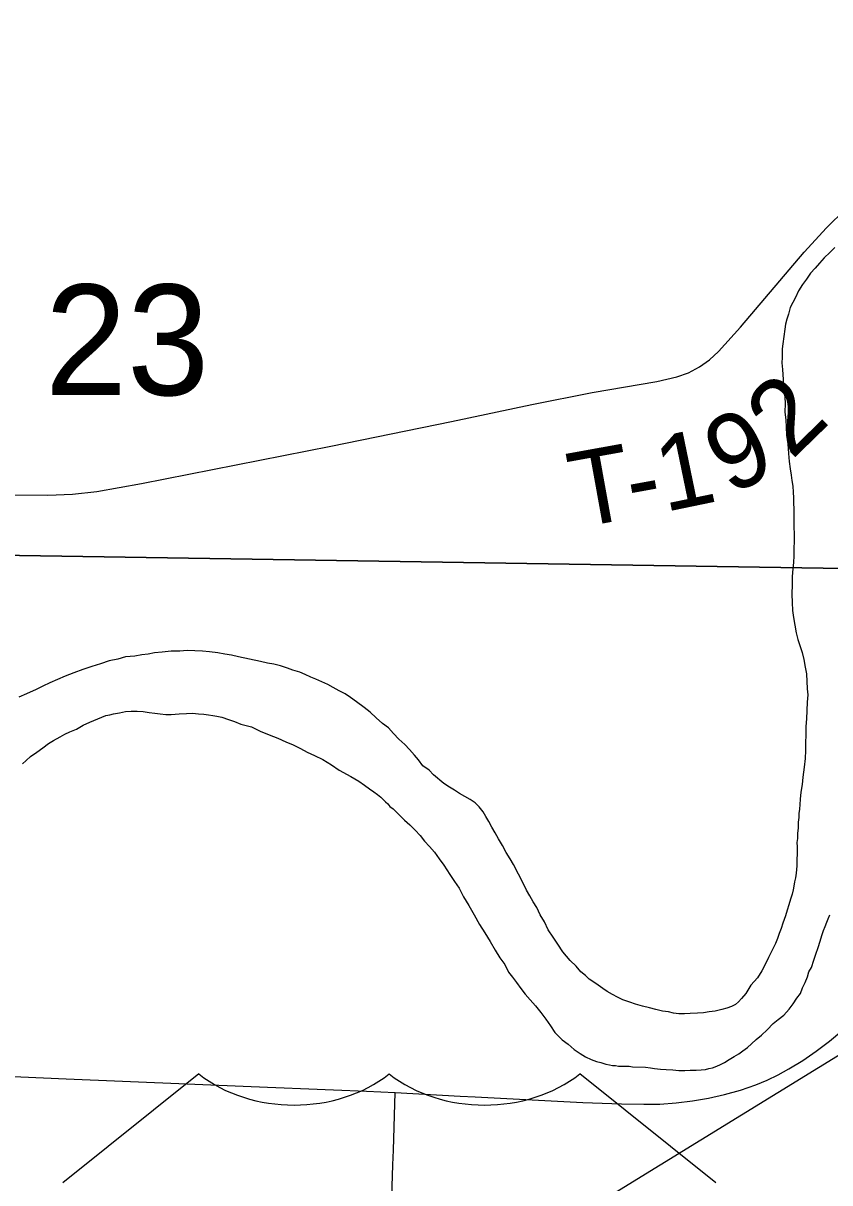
# Model space of a CAD drawing. Extents: x 2.4 to 73.1, y 4.5 to 25.6.
# Drawn here: x 30.0992 to 30.4044, y 20.9019 to 21.3407 of the extents above; entities that cross this region are included whole.
import ezdxf

# ---------------------------------------------------------------- set-up
doc = ezdxf.new("R2010")
doc.units = 0
for name, color, linetype in [('GM_X_County_Road', 7, 'Continuous'), ('GM_X_Major_River', 7, 'Continuous'), ('GM_X_Rail_Line', 7, 'Continuous'), ('GM_X_Section', 7, 'Continuous'), ('GM_X_Section_Text', 7, 'Continuous'), ('GM_X_Township_Road', 7, 'Continuous'), ('GM_X_Township_Road_Text', 7, 'Continuous'), ('GM_X_US_Route', 7, 'Continuous'), ('GM_X_US_Shield', 7, 'Continuous')]:
    doc.layers.add(name, color=color, linetype=linetype)

msp = doc.modelspace()

# ---------------------------------------------------------------- linework, layer by layer
at = {"layer": 'GM_X_County_Road'}
for points in [[(29.98929, 20.94555), (29.98973, 20.94555), (30.01271, 20.94578), (30.02518, 20.94536), (30.0781, 20.9429), (30.11546, 20.94119), (30.18551, 20.93827), (30.21656, 20.93706)], [(30.21656, 20.93706), (30.22911, 20.93657), (30.23998, 20.93603)]]:
    msp.add_lwpolyline(points, dxfattribs=at)
at = {"layer": 'GM_X_Major_River'}
for points in [[(30.40633, 21.25576), (30.40439, 21.2539), (30.40225, 21.25186), (30.40049, 21.24981), (30.39893, 21.24795), (30.39718, 21.24609), (30.39561, 21.24384), (30.39404, 21.24179), (30.39265, 21.23935), (30.39146, 21.23691), (30.39047, 21.23503), (30.38947, 21.23315), (30.38884, 21.23051), (30.38823, 21.22862), (30.38762, 21.22674), (30.38739, 21.22484), (30.38669, 21.21935), (30.38646, 21.21745), (30.38642, 21.21575), (30.38639, 21.21423), (30.38634, 21.21214), (30.38647, 21.20967), (30.38662, 21.20776), (30.38677, 21.20586), (30.38691, 21.20358), (30.38705, 21.20148), (30.38738, 21.1992), (30.38751, 21.19672), (30.38744, 21.1935), (30.38776, 21.19064), (30.38788, 21.18779), (30.38801, 21.18475), (30.3885, 21.1815), (30.3888, 21.17789), (30.38911, 21.17484), (30.38943, 21.17199), (30.38976, 21.1697), (30.39009, 21.1676), (30.39042, 21.1655), (30.39056, 21.16322), (30.39071, 21.16113), (30.39066, 21.15904), (30.3908, 21.15695), (30.39076, 21.15486), (30.39088, 21.15201), (30.39083, 21.14992), (30.39097, 21.14745), (30.39091, 21.14479), (30.39084, 21.14175), (30.39078, 21.13909)], [(30.39078, 21.13909), (30.39073, 21.13662), (30.39048, 21.13416), (30.39023, 21.13131), (30.39016, 21.12828), (30.39008, 21.12467), (30.39019, 21.12144), (30.39032, 21.1184), (30.39064, 21.11573), (30.39114, 21.11287), (30.39165, 21.11001), (30.39235, 21.10752), (30.39306, 21.10522), (30.39395, 21.10255), (30.39465, 21.09987), (30.39516, 21.09701), (30.39567, 21.09453), (30.39593, 21.08882), (30.39606, 21.08654), (30.39581, 21.0837), (30.39574, 21.08066), (30.39567, 21.07743), (30.39542, 21.07459), (30.39534, 21.07136), (30.39527, 21.06832), (30.39521, 21.06547), (30.39514, 21.06243), (30.39469, 21.05922), (30.39423, 21.05543), (30.39397, 21.05258), (30.39353, 21.04974), (30.39328, 21.04709), (30.39304, 21.04501), (30.393, 21.0433), (30.39277, 21.04159), (30.39274, 21.04007), (30.39251, 21.03837), (30.39246, 21.03609), (30.39223, 21.0342), (30.39218, 21.03211), (30.39196, 21.03059), (30.39211, 21.02907), (30.39207, 21.02698), (30.39204, 21.02584), (30.39201, 21.0247), (30.39198, 21.02337), (30.39195, 21.02185), (30.3917, 21.01901), (30.39147, 21.01731), (30.39105, 21.0158), (30.39082, 21.01409), (30.3906, 21.01277), (30.39019, 21.01107), (30.38957, 21.00918), (30.38896, 21.0071), (30.38834, 21.00503), (30.38772, 21.00295), (30.38671, 21.00013), (30.38609, 20.99805), (30.38529, 20.99617), (30.38468, 20.99428), (30.38387, 20.9924), (30.38128, 20.98714), (30.38009, 20.9847), (30.3787, 20.98207), (30.37712, 20.97945), (30.37458, 20.97666), (30.37261, 20.97347), (30.37105, 20.97161), (30.36988, 20.9703), (30.36872, 20.96938), (30.36718, 20.96865), (30.36545, 20.96793), (30.36354, 20.96741), (30.36106, 20.96689), (30.35877, 20.96657), (30.35667, 20.96623), (30.35439, 20.96609), (30.35153, 20.96597), (30.34944, 20.96583), (30.34735, 20.96587), (30.34526, 20.96611), (30.34337, 20.96653), (30.34109, 20.96677), (30.33864, 20.9674), (30.33618, 20.96803), (30.33353, 20.96866), (30.33089, 20.96947), (30.32882, 20.97028), (30.32617, 20.9711), (30.3241, 20.9721), (30.32223, 20.97309), (30.32016, 20.97428), (30.31848, 20.97545), (30.31679, 20.97663), (30.31511, 20.97781), (30.31342, 20.97899), (30.31193, 20.98035), (30.31025, 20.98172), (30.3084, 20.98385), (30.30617, 20.98599)], [(30.30617, 20.98599), (30.30339, 20.98928), (30.30155, 20.99217), (30.29971, 20.99487), (30.29787, 20.99757), (30.29642, 21.00065), (30.29477, 21.00334), (30.2935, 21.00603), (30.29222, 21.00815), (30.29094, 21.01046), (30.28965, 21.01258), (30.28857, 21.01507), (30.28474, 21.02238), (30.28346, 21.0245), (30.28199, 21.02681), (30.28053, 21.0295), (30.27906, 21.032), (30.27778, 21.03431), (30.2765, 21.03643), (30.27541, 21.03855), (30.27431, 21.04047), (30.27321, 21.0422), (30.27173, 21.04414), (30.27025, 21.04569), (30.26837, 21.04687), (30.26424, 21.04924), (30.26237, 21.05043), (30.26049, 21.05161), (30.25843, 21.05299), (30.25451, 21.0563), (30.25284, 21.05805), (30.25041, 21.05963), (30.24875, 21.06194), (30.24727, 21.06369), (30.24541, 21.06582), (30.24356, 21.06776), (30.24132, 21.06971), (30.23928, 21.07184), (30.23742, 21.07398), (30.23518, 21.07574), (30.23276, 21.07788), (30.23052, 21.08002), (30.22828, 21.08178), (30.22529, 21.08394), (30.22304, 21.08551), (30.22098, 21.08688), (30.21873, 21.08807), (30.21647, 21.08926), (30.21441, 21.09045), (30.21215, 21.09145), (30.20989, 21.09245), (30.20801, 21.09325), (30.20594, 21.09425), (30.20387, 21.09506), (30.20122, 21.09588), (30.19915, 21.09668), (30.19651, 21.0975), (30.19405, 21.09813), (30.19159, 21.09856), (30.18894, 21.09919), (30.18061, 21.1009), (30.17797, 21.10153), (30.17551, 21.10197), (30.17285, 21.1024), (30.16963, 21.10286), (30.16698, 21.10311), (30.16413, 21.10317), (30.16128, 21.10324), (30.15842, 21.10311), (30.15519, 21.10299), (30.15176, 21.10269), (30.1489, 21.10237), (30.14642, 21.10186), (30.14413, 21.10172), (30.14146, 21.10121), (30.13784, 21.10091), (30.13497, 21.10003), (30.13172, 21.09934), (30.12846, 21.09827), (30.12521, 21.09721), (30.12176, 21.09615), (30.11831, 21.09489), (30.11505, 21.09364), (30.11217, 21.09237), (30.10929, 21.09111), (30.1066, 21.08984), (30.1041, 21.08857), (30.10046, 21.08694), (30.09758, 21.08567)], [(30.09891, 21.06038), (30.10027, 21.06168), (30.10201, 21.06316), (30.10433, 21.06481), (30.10665, 21.06647), (30.10878, 21.06813), (30.1107, 21.06923), (30.11321, 21.07069), (30.11494, 21.0716), (30.11686, 21.07251), (30.11936, 21.07359), (30.12186, 21.07506), (30.12436, 21.07614), (30.1305, 21.07866), (30.13203, 21.07901), (30.13336, 21.07936), (30.13565, 21.07969), (30.13795, 21.0802), (30.14004, 21.08035), (30.14232, 21.0803), (30.1446, 21.08025), (30.14687, 21.07981), (30.14896, 21.07958), (30.15104, 21.07934), (30.15313, 21.0791), (30.15522, 21.07906), (30.15674, 21.07921), (30.15827, 21.07937), (30.16093, 21.0795), (30.16322, 21.07964), (30.16549, 21.0794), (30.16758, 21.07916), (30.16928, 21.07893), (30.17099, 21.0787), (30.17251, 21.07848), (30.1744, 21.07805), (30.17685, 21.07724), (30.17911, 21.07643), (30.18156, 21.07542), (30.18553, 21.07438), (30.18892, 21.07279), (30.19231, 21.07138), (30.19551, 21.07017), (30.19852, 21.06877), (30.20135, 21.06757), (30.20417, 21.06618), (30.20661, 21.06479), (30.20943, 21.06359), (30.21263, 21.062), (30.21582, 21.06002), (30.21881, 21.05806), (30.22313, 21.05568), (30.22614, 21.0539), (30.22838, 21.05233), (30.23025, 21.05096), (30.23194, 21.04978), (30.23324, 21.0488), (30.23455, 21.04782), (30.23623, 21.04608), (30.23716, 21.0453), (30.2379, 21.04433), (30.23921, 21.04335), (30.24348, 21.03908), (30.24553, 21.03732), (30.24758, 21.03537), (30.24943, 21.03324), (30.2511, 21.03111), (30.25296, 21.02917), (30.25481, 21.02704)], [(30.25481, 21.02704), (30.25665, 21.02453), (30.25831, 21.02202), (30.2607, 21.01855), (30.26235, 21.01585), (30.2642, 21.01334), (30.26583, 21.01008), (30.26785, 21.0068), (30.26987, 21.00334), (30.27187, 20.99968), (30.27389, 20.99641), (30.27591, 20.99313), (30.27774, 20.98986), (30.27957, 20.98697), (30.28142, 20.98446), (30.28287, 20.98158), (30.28435, 20.97964), (30.28583, 20.97771), (30.28749, 20.97539), (30.28915, 20.97327), (30.291, 20.97113), (30.29304, 20.96881), (30.29508, 20.96629), (30.29692, 20.96378), (30.29877, 20.96127), (30.30042, 20.95877), (30.30321, 20.95604), (30.30545, 20.95428), (30.30769, 20.95233), (30.30994, 20.95076), (30.312, 20.94957), (30.31407, 20.94858), (30.31614, 20.94777), (30.31784, 20.94735), (30.31973, 20.94674), (30.32106, 20.94652), (30.32219, 20.94631), (30.32333, 20.94628), (30.32447, 20.94606), (30.32618, 20.94602), (30.32713, 20.946), (30.32846, 20.94597), (30.32979, 20.94575), (30.33473, 20.94564), (30.33662, 20.94541), (30.33814, 20.94518), (30.34041, 20.94494), (30.3425, 20.94471), (30.34497, 20.94465), (30.34725, 20.94441), (30.34953, 20.94436), (30.35162, 20.9445), (30.3539, 20.94445), (30.3558, 20.9446), (30.35733, 20.94475), (30.35867, 20.9451), (30.36001, 20.94545), (30.36173, 20.94598), (30.36308, 20.94671), (30.36461, 20.94744), (30.36635, 20.94854), (30.36827, 20.94963), (30.37001, 20.95073), (30.37156, 20.95184), (30.3733, 20.95313), (30.37485, 20.95442), (30.37659, 20.95609), (30.37853, 20.95776), (30.38067, 20.9598), (30.383, 20.96222), (30.38494, 20.96369), (30.38707, 20.96536), (30.38902, 20.96759), (30.39059, 20.96965), (30.39196, 20.9717), (30.39334, 20.97357), (30.39414, 20.97564), (30.39514, 20.97771), (30.39595, 20.97978), (30.39656, 20.98167), (30.39755, 20.98335), (30.39837, 20.98618), (30.39918, 20.98845), (30.4, 20.9909), (30.40082, 20.99335), (30.40143, 20.99542), (30.40204, 20.99731), (30.40265, 20.99882), (30.40326, 21.00051), (30.40386, 21.00183), (30.40446, 21.00334)]]:
    msp.add_lwpolyline(points, dxfattribs=at)
at = {"layer": 'GM_X_Rail_Line'}
msp.add_lwpolyline([(29.78044, 20.47651), (29.7911, 20.50784), (29.80268, 20.53672), (29.81269, 20.55779), (29.82231, 20.57304), (29.83822, 20.59181), (29.85825, 20.60693), (29.8919, 20.62838), (30.25114, 20.85389), (30.44465, 20.9729), (30.47522, 20.99321), (30.50027, 21.01391), (30.52076, 21.03709), (30.54176, 21.06437), (30.56209, 21.09275), (30.63339, 21.20115), (30.72595, 21.34181), (30.80047, 21.46311), (30.8477, 21.53019), (30.87537, 21.57343), (30.91427, 21.643)], dxfattribs=at)
at = {"layer": 'GM_X_Section'}
for points in [[(30.51643, 21.65196), (30.49787, 21.13293), (29.99357, 21.14088), (30.01225, 21.66591), (30.01568, 21.66582)], [(30.48067, 20.63017), (29.97714, 20.63847), (29.99357, 21.14088), (30.49787, 21.13293)]]:
    msp.add_lwpolyline(points, close=True, dxfattribs=at)
at = {"layer": 'GM_X_Township_Road'}
msp.add_lwpolyline([(30.03239, 21.16265), (30.10852, 21.16211), (30.11784, 21.16246), (30.12709, 21.16351), (30.14392, 21.16648), (30.21557, 21.18059), (30.26124, 21.18992), (30.29162, 21.19639), (30.31449, 21.20089), (30.33899, 21.20509), (30.34656, 21.20684), (30.35094, 21.20842), (30.35506, 21.21059), (30.35885, 21.21329), (30.3623, 21.21641), (30.37068, 21.2256), (30.39475, 21.25408), (30.40318, 21.26321), (30.41762, 21.27733)], dxfattribs=at)
at = {"layer": 'GM_X_US_Route'}
for points in [[(30.23998, 20.93603), (30.2645, 20.93472), (30.27026, 20.93441), (30.31092, 20.93233), (30.32557, 20.93174), (30.33401, 20.93165), (30.34014, 20.93167), (30.34632, 20.93217), (30.35247, 20.93292), (30.35858, 20.93394), (30.36463, 20.93526), (30.37058, 20.93693), (30.37642, 20.93897), (30.38071, 20.94074), (30.38489, 20.94274), (30.38896, 20.94495), (30.39423, 20.9482), (30.39933, 20.95172), (30.40427, 20.95545), (30.40899, 20.95945)], [(30.2295, 20.6017), (30.22957, 20.60423), (30.23001, 20.6142), (30.23051, 20.62744), (30.2307, 20.63379), (30.23314, 20.71446), (30.23608, 20.81081), (30.23773, 20.86365), (30.23909, 20.90872), (30.23932, 20.9142), (30.23998, 20.93603)]]:
    msp.add_lwpolyline(points, dxfattribs=at)
at = {"layer": 'GM_X_US_Shield'}
for p, q in [((30.16563, 20.94308), (30.11413, 20.90188)), ((30.36132, 20.90188), (30.30982, 20.94308))]:
    msp.add_line(p, q, dxfattribs=at)
for centre in [(30.20167, 20.9725), (30.27377, 20.9725)]:
    msp.add_ellipse(centre, major_axis=(-0.0515, 0), ratio=0.8, start_param=0.795399, end_param=2.346194, dxfattribs=at)

# ---------------------------------------------------------------- texts
at = {"layer": 'GM_X_Section_Text'}
msp.add_text('23', height=0.041856, rotation=0, dxfattribs=at).set_placement((30.10736, 21.19993))
at = {"layer": 'GM_X_Township_Road_Text'}
for s, rotation, p in [('2', 44.2651, (30.38999, 21.17515)), ('9', 26.5661, (30.36657, 21.1618)), ('1', 11.6884, (30.34186, 21.15563)), ('T', 10.2588, (30.30871, 21.14959)), ('-', 10.3727, (30.32968, 21.15339))]:
    msp.add_text(s, height=0.02841, rotation=rotation, dxfattribs=at).set_placement(p)

doc.saveas('drawing.dxf')
